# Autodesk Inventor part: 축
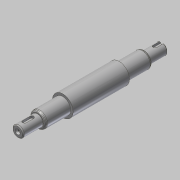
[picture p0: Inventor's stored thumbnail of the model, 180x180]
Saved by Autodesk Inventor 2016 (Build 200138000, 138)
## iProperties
Created: 2019-06
Part Number: 축
Material: 강철, 연강
Document SubType Name: Modeling
Designer: mduedu
Density: 1 g/cm^3
Appearance: 강철
Author: mduedu
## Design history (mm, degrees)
sketch "스케치1"
  geometry: L1 (0, 0)-(21, 0); L2 (21, 0)-(21, 6); L3 (21, 6)-(0, 6); L4 (0, 6)-(0, 0); L5 (21, 0)-(48, 0); L6 (48, 0)-(48, 8.5); L7 (48, 8.5)-(21, 8.5); L8 (21, 8.5)-(21, 0); L9 (48, 0)-(108, 0); L10 (108, 0)-(108, 11); L11 (108, 11)-(48, 11); L12 (48, 11)-(48, 0); L13 (108, 0)-(135, 0); L14 (135, 0)-(135, 8.5); L15 (135, 8.5)-(108, 8.5); L16 (108, 8.5)-(108, 0); L17 (135, 0)-(154, 0); L18 (154, 0)-(154, 6); L19 (154, 6)-(135, 6); L20 (135, 6)-(135, 0)
  constraints: 40 end point, 10 parallel, 5 horizontal, 5 perpendicular
  dimensions: "d3" = 60 distance of L10.end L11.end; "d4" = 17 diameter of L15 L13; "d5" = 22 diameter of L11 L9; "d6" = 17 diameter of L7 L5; "d7" = 12 diameter of L3 L1; "d40" = 19 distance of L18.end L19.end; "d41" = 12 diameter of L19 L17; "d42" = 46 distance between parallel lines of L10 L18; "d43" = 133 distance between parallel lines of L8 L18; "d44" = 154 distance between parallel lines of L4 L18
revolve "회전1" sketch "스케치1" stored, may be unused: angle "d9" = 90 deg
node "작업 평면1"
sketch "스케치2" dims "d10" = 12
  geometry: L1 (3.5, -2)-(-4.5, -2); L2 (-4.5, -2)-(-4.5, 2); L3 (-4.5, 2)-(3.5, 2); L4 (3.5, 2)-(3.5, -2); L5 (-10.5, 8.5)-(-10.5, -8.5) reference; 3 further points
  constraints: 8 end point, 2 midpoint, 2 parallel, 2 vertical alignment, 1 horizontal, 1 horizontal alignment, 1 perpendicular, 4 other
  dimensions: "d12" = 4 dimension on L5; "d13" = 4 distance between parallel lines of L3 L1
extrude "돌출1" cut sketch "스케치2" distance "d14" = 2.5; taper "d15" = 0 deg
sketch "스케치4"
  geometry: L1 (-143.5, 2)-(-135.5, 2); L2 (-135.5, 2)-(-135.5, -2); L3 (-135.5, -2)-(-143.5, -2); L4 (-143.5, -2)-(-143.5, 2); L5 (-143.5, 6)-(-143.5, -6) reference; 2 further points
  constraints: 8 end point, 2 parallel, 1 collinear, 1 horizontal, 1 horizontal alignment, 1 midpoint, 1 perpendicular, 1 vertical alignment, 2 other
  dimensions: "d50" = 10 dimension on L4; "d52" = 4 distance between parallel lines of L1 L3
extrude "돌출2" cut sketch "스케치4" distance "d53" = 2.5; taper "d54" = 0 deg
hole "구멍1" diameter "d18" = 3.242; stored, may be unused: countersink angle "d22" = 90 deg, drill point angle "d24" = 118 deg; dims "d16" = 10, "d17" = 10, "d19" = 8, "d20" = 4, "d21" = 2, "d23" = 10
sketch "스케치3"
  geometry: L1 (0, 0)-(2, 0); L2 (2, 0)-(2, -1.621); L3 (0, -2.776)-(0, 0); L4 (10, -1.621)-(0, -1.621) reference; L5 (0, -2.776)-(2, -1.621)
  constraints: 8 end point, 1 horizontal, 1 parallel, 1 perpendicular, 1 point on line
  dimensions: "d25" = 2 distance between parallel lines of L2 L3; "d27" = 30 deg angle of L1 L5
revolve "회전2" sketch "스케치3" stored, may be unused: angle "d29" = 90 deg
chamfer "모따기1" distance "d30" = 1.82; stored, may be unused: second distance "d31" = 2, angle "d32" = 30 deg
fillet "모깎기1" dims "d36" = 2, "d37" = 1
chamfer "모따기3" distance "d45" = 1.82; stored, may be unused: second distance "d46" = 2, angle "d47" = 30 deg
fillet "모깎기2" dims "d48" = 2, "d49" = 1
chamfer "모따기4" distance "d55" = 1; stored, may be unused: second distance "d56" = 2, angle "d57" = 30 deg
node "솔리드1"
